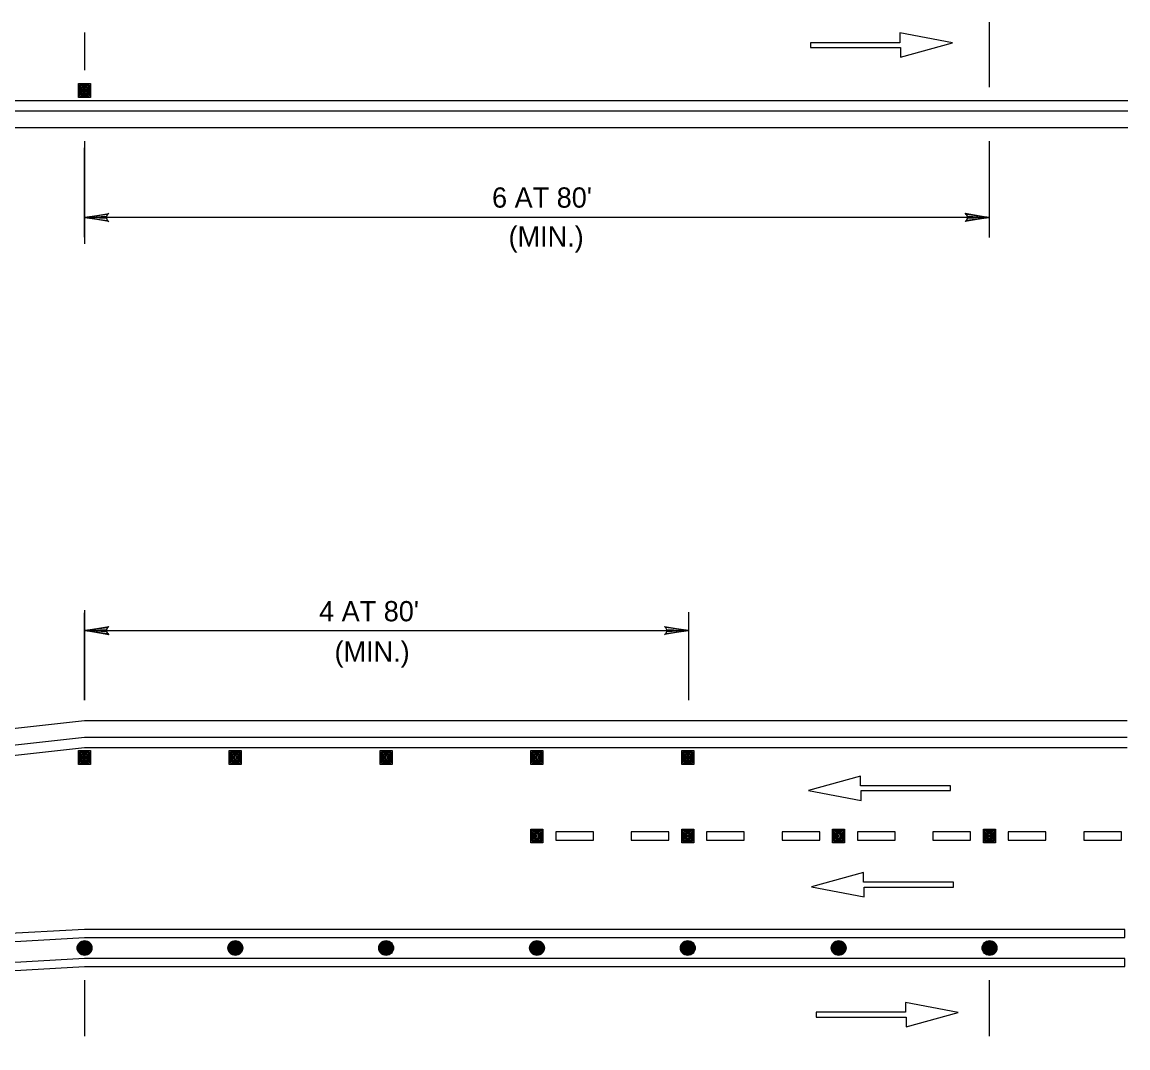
# Model space of a CAD drawing. Extents: x 639362 to 641108, y 298458 to 299646.
# Drawn here: x 639788.7 to 639952.7, y 298599.3 to 298751.3 of the extents above; entities that cross this region are included whole.
import ezdxf

# ---------------------------------------------------------------- set-up
doc = ezdxf.new("R2010")
doc.units = 0
doc.layers.add('2', color=7, linetype='Continuous')
doc.layers.add('3', color=7, linetype='Continuous')

# ---------------------------------------------------------------- blocks, each defined once
blk = doc.blocks.new('RARROW')
at = {"layer": '3'}
blk.add_lwpolyline([(-2.2695, 0.285), (-2.184875, 0.12075), (0, 0), (-2.2695, 0.285), (-2.38575, 0.384625), (0, 0), (-2.183125, -0.108), (-2.262875, -0.2705), (0, 0), (-2.38575, -0.379125), (-2.262875, -0.2705)], dxfattribs=at)

msp = doc.modelspace()

# ---------------------------------------------------------------- linework, layer by layer
at = {"layer": '2'}
for p, q in [((639932.2, 298741.66), (639932.2, 298751.3)), ((639798, 298749.76), (639798, 298744.18)), ((639926.74, 298748.22), (639918.93, 298749.7)), ((639918.93, 298749.7), (639918.93, 298748.25)), ((639918.93, 298748.25), (639905.69, 298748.25)), ((639905.69, 298748.25), (639905.69, 298747.55)), ((639905.69, 298747.55), (639919.02, 298747.55)), ((639919.02, 298746.1), (639926.74, 298748.22)), ((639919.02, 298747.55), (639919.02, 298746.1)), ((639797.11, 298740.14), (639797.11, 298742.18)), ((639797.11, 298742.18), (639798.88, 298742.18)), ((639797.28, 298740.32), (639797.28, 298742)), ((639797.28, 298742), (639798.7, 298742)), ((639797.46, 298740.5), (639797.46, 298741.83)), ((639797.46, 298741.83), (639798.53, 298741.83)), ((639797.64, 298740.67), (639797.64, 298741.65)), ((639797.64, 298741.65), (639798.35, 298741.65)), ((639797.82, 298740.85), (639797.82, 298741.47)), ((639797.82, 298741.47), (639798.17, 298741.47)), ((639798, 298741.03), (639798, 298741.29)), ((639798.17, 298741.47), (639798.17, 298740.85)), ((639798.35, 298741.65), (639798.35, 298740.67)), ((639798.53, 298741.83), (639798.53, 298740.5)), ((639798.7, 298742), (639798.7, 298740.32)), ((639798.88, 298742.18), (639798.88, 298740.14)), ((639431.35, 298739.66), (639952.74, 298739.66)), ((639798.88, 298740.14), (639797.11, 298740.14)), ((639798.7, 298740.32), (639797.28, 298740.32)), ((639798.53, 298740.5), (639797.46, 298740.5)), ((639798.35, 298740.67), (639797.64, 298740.67)), ((639798.17, 298740.85), (639797.82, 298740.85)), ((639431.35, 298738.16), (639952.74, 298738.16)), ((639431.35, 298735.66), (639952.74, 298735.66)), ((639798, 298733.66), (639798, 298718.46)), ((639932.2, 298719.36), (639932.2, 298733.66)), ((639798, 298719.43), (639798, 298732.66)), ((639932.2, 298722.36), (639798, 298722.36)), ((639797.99, 298664.16), (639797.99, 298650.81)), ((639798, 298650.81), (639798, 298663.74)), ((639887.61, 298650.81), (639887.61, 298663.83)), ((639798.01, 298661.11), (639887.61, 298661.11)), ((639585.9, 298624.2), (639797.99, 298647.81)), ((639797.99, 298647.81), (639951.12, 298647.81)), ((639797.99, 298647.81), (639952.64, 298647.81)), ((639585.9, 298621.7), (639797.99, 298645.31)), ((639797.99, 298645.31), (639951.12, 298645.31)), ((639797.99, 298645.31), (639952.64, 298645.31)), ((639585.9, 298620.2), (639797.99, 298643.81)), ((639797.11, 298641.29), (639797.11, 298643.33)), ((639797.11, 298643.33), (639798.88, 298643.33)), ((639797.28, 298641.47), (639797.28, 298643.16)), ((639797.28, 298643.16), (639798.7, 298643.16)), ((639797.46, 298641.65), (639797.46, 298642.98)), ((639797.46, 298642.98), (639798.53, 298642.98)), ((639797.64, 298641.83), (639797.64, 298642.8)), ((639797.64, 298642.8), (639798.35, 298642.8)), ((639797.82, 298642), (639797.82, 298642.62)), ((639797.82, 298642.62), (639798.17, 298642.62)), ((639797.99, 298643.81), (639951.12, 298643.81)), ((639797.99, 298643.81), (639952.64, 298643.81)), ((639798.17, 298642.62), (639798.17, 298642)), ((639798.35, 298642.8), (639798.35, 298641.83)), ((639798.53, 298642.98), (639798.53, 298641.65)), ((639798.7, 298643.16), (639798.7, 298641.47)), ((639798.88, 298643.33), (639798.88, 298641.29)), ((639819.47, 298641.29), (639819.47, 298643.33)), ((639819.47, 298643.33), (639821.25, 298643.33)), ((639819.65, 298641.47), (639819.65, 298643.16)), ((639819.65, 298643.16), (639821.07, 298643.16)), ((639819.83, 298641.65), (639819.83, 298642.98)), ((639819.83, 298642.98), (639820.89, 298642.98)), ((639820.01, 298641.83), (639820.01, 298642.8)), ((639820.01, 298642.8), (639820.72, 298642.8)), ((639820.18, 298642), (639820.18, 298642.62)), ((639820.18, 298642.62), (639820.54, 298642.62)), ((639820.54, 298642.62), (639820.54, 298642)), ((639820.72, 298642.8), (639820.72, 298641.83)), ((639820.89, 298642.98), (639820.89, 298641.65)), ((639821.07, 298643.16), (639821.07, 298641.47)), ((639821.25, 298643.33), (639821.25, 298641.29)), ((639841.84, 298641.29), (639841.84, 298643.33)), ((639841.84, 298643.33), (639843.62, 298643.33)), ((639842.02, 298641.47), (639842.02, 298643.16)), ((639842.02, 298643.16), (639843.44, 298643.16)), ((639842.2, 298641.65), (639842.2, 298642.98)), ((639842.2, 298642.98), (639843.26, 298642.98)), ((639842.37, 298641.83), (639842.37, 298642.8)), ((639842.37, 298642.8), (639843.08, 298642.8)), ((639842.55, 298642), (639842.55, 298642.62)), ((639842.55, 298642.62), (639842.91, 298642.62)), ((639842.91, 298642.62), (639842.91, 298642)), ((639843.08, 298642.8), (639843.08, 298641.83)), ((639843.26, 298642.98), (639843.26, 298641.65)), ((639843.44, 298643.16), (639843.44, 298641.47)), ((639843.62, 298643.33), (639843.62, 298641.29)), ((639864.21, 298641.29), (639864.21, 298643.33)), ((639864.21, 298643.33), (639865.98, 298643.33)), ((639864.39, 298641.47), (639864.39, 298643.16)), ((639864.39, 298643.16), (639865.81, 298643.16)), ((639864.56, 298641.65), (639864.56, 298642.98)), ((639864.56, 298642.98), (639865.63, 298642.98)), ((639864.74, 298641.83), (639864.74, 298642.8)), ((639864.74, 298642.8), (639865.45, 298642.8)), ((639864.92, 298642), (639864.92, 298642.62)), ((639864.92, 298642.62), (639865.27, 298642.62)), ((639865.27, 298642.62), (639865.27, 298642)), ((639865.45, 298642.8), (639865.45, 298641.83)), ((639865.63, 298642.98), (639865.63, 298641.65)), ((639865.81, 298643.16), (639865.81, 298641.47)), ((639865.98, 298643.33), (639865.98, 298641.29)), ((639886.58, 298641.29), (639886.58, 298643.33)), ((639886.58, 298643.33), (639888.35, 298643.33)), ((639886.75, 298641.47), (639886.75, 298643.16)), ((639886.75, 298643.16), (639888.17, 298643.16)), ((639886.93, 298641.65), (639886.93, 298642.98)), ((639886.93, 298642.98), (639888, 298642.98)), ((639887.11, 298641.83), (639887.11, 298642.8)), ((639887.11, 298642.8), (639887.82, 298642.8)), ((639887.29, 298642), (639887.29, 298642.62)), ((639887.29, 298642.62), (639887.64, 298642.62)), ((639887.64, 298642.62), (639887.64, 298642)), ((639887.82, 298642.8), (639887.82, 298641.83)), ((639888, 298642.98), (639888, 298641.65)), ((639888.17, 298643.16), (639888.17, 298641.47)), ((639888.35, 298643.33), (639888.35, 298641.29)), ((639798.88, 298641.29), (639797.11, 298641.29)), ((639798.7, 298641.47), (639797.28, 298641.47)), ((639798.53, 298641.65), (639797.46, 298641.65)), ((639798.35, 298641.83), (639797.64, 298641.83)), ((639798.17, 298642), (639797.82, 298642)), ((639798, 298642.18), (639798, 298642.45)), ((639821.25, 298641.29), (639819.47, 298641.29)), ((639821.07, 298641.47), (639819.65, 298641.47)), ((639820.89, 298641.65), (639819.83, 298641.65)), ((639820.72, 298641.83), (639820.01, 298641.83)), ((639820.54, 298642), (639820.18, 298642)), ((639820.36, 298642.18), (639820.36, 298642.45)), ((639843.62, 298641.29), (639841.84, 298641.29)), ((639843.44, 298641.47), (639842.02, 298641.47)), ((639843.26, 298641.65), (639842.2, 298641.65)), ((639843.08, 298641.83), (639842.37, 298641.83)), ((639842.91, 298642), (639842.55, 298642)), ((639842.73, 298642.18), (639842.73, 298642.45)), ((639865.98, 298641.29), (639864.21, 298641.29)), ((639865.81, 298641.47), (639864.39, 298641.47)), ((639865.63, 298641.65), (639864.56, 298641.65)), ((639865.45, 298641.83), (639864.74, 298641.83)), ((639865.27, 298642), (639864.92, 298642)), ((639865.1, 298642.18), (639865.1, 298642.45)), ((639888.35, 298641.29), (639886.58, 298641.29)), ((639888.17, 298641.47), (639886.75, 298641.47)), ((639888, 298641.65), (639886.93, 298641.65)), ((639887.82, 298641.83), (639887.11, 298641.83)), ((639887.64, 298642), (639887.29, 298642)), ((639887.47, 298642.18), (639887.47, 298642.45)), ((639913.08, 298639.53), (639905.36, 298637.42)), ((639913.08, 298638.09), (639913.08, 298639.53)), ((639926.41, 298638.09), (639913.08, 298638.09)), ((639926.41, 298637.39), (639926.41, 298638.09)), ((639905.36, 298637.42), (639913.16, 298635.94)), ((639913.16, 298635.94), (639913.16, 298637.39)), ((639913.16, 298637.39), (639926.41, 298637.39)), ((639864.21, 298629.65), (639864.21, 298631.69)), ((639864.21, 298631.69), (639865.98, 298631.69)), ((639864.39, 298629.83), (639864.39, 298631.51)), ((639864.39, 298631.51), (639865.81, 298631.51)), ((639864.56, 298630), (639864.56, 298631.33)), ((639864.56, 298631.33), (639865.63, 298631.33)), ((639864.74, 298630.18), (639864.74, 298631.15)), ((639864.74, 298631.15), (639865.45, 298631.15)), ((639865.45, 298631.15), (639865.45, 298630.18)), ((639865.63, 298631.33), (639865.63, 298630)), ((639865.81, 298631.51), (639865.81, 298629.83)), ((639865.98, 298631.69), (639865.98, 298629.65)), ((639873.49, 298631.27), (639867.89, 298631.27)), ((639867.89, 298631.27), (639867.89, 298630.07)), ((639873.49, 298630.07), (639873.49, 298631.27)), ((639884.67, 298631.27), (639879.08, 298631.27)), ((639879.08, 298631.27), (639879.08, 298630.07)), ((639884.67, 298630.07), (639884.67, 298631.27)), ((639886.58, 298629.65), (639886.58, 298631.69)), ((639886.58, 298631.69), (639888.35, 298631.69)), ((639886.75, 298629.83), (639886.75, 298631.51)), ((639886.75, 298631.51), (639888.17, 298631.51)), ((639886.93, 298630), (639886.93, 298631.33)), ((639886.93, 298631.33), (639888, 298631.33)), ((639887.11, 298630.18), (639887.11, 298631.15)), ((639887.11, 298631.15), (639887.82, 298631.15)), ((639887.82, 298631.15), (639887.82, 298630.18)), ((639888, 298631.33), (639888, 298630)), ((639888.17, 298631.51), (639888.17, 298629.83)), ((639888.35, 298631.69), (639888.35, 298629.65)), ((639895.85, 298631.27), (639890.26, 298631.27)), ((639890.26, 298631.27), (639890.26, 298630.07)), ((639895.85, 298630.07), (639895.85, 298631.27)), ((639907.04, 298631.27), (639901.45, 298631.27)), ((639901.45, 298631.27), (639901.45, 298630.07)), ((639907.04, 298630.07), (639907.04, 298631.27)), ((639908.94, 298629.65), (639908.94, 298631.69)), ((639908.94, 298631.69), (639910.72, 298631.69)), ((639909.12, 298629.83), (639909.12, 298631.51)), ((639909.12, 298631.51), (639910.54, 298631.51)), ((639909.3, 298630), (639909.3, 298631.33)), ((639909.3, 298631.33), (639910.36, 298631.33)), ((639909.48, 298630.18), (639909.48, 298631.15)), ((639909.48, 298631.15), (639910.19, 298631.15)), ((639910.19, 298631.15), (639910.19, 298630.18)), ((639910.36, 298631.33), (639910.36, 298630)), ((639910.54, 298631.51), (639910.54, 298629.83)), ((639910.72, 298631.69), (639910.72, 298629.65)), ((639918.22, 298631.27), (639912.63, 298631.27)), ((639912.63, 298631.27), (639912.63, 298630.07)), ((639918.22, 298630.07), (639918.22, 298631.27)), ((639929.41, 298631.27), (639923.81, 298631.27)), ((639923.81, 298631.27), (639923.81, 298630.07)), ((639929.41, 298630.07), (639929.41, 298631.27)), ((639931.31, 298629.65), (639931.31, 298631.69)), ((639931.31, 298631.69), (639933.09, 298631.69)), ((639931.49, 298629.83), (639931.49, 298631.51)), ((639931.49, 298631.51), (639932.91, 298631.51)), ((639931.67, 298630), (639931.67, 298631.33)), ((639931.67, 298631.33), (639932.73, 298631.33)), ((639931.84, 298630.18), (639931.84, 298631.15)), ((639931.84, 298631.15), (639932.55, 298631.15)), ((639932.55, 298631.15), (639932.55, 298630.18)), ((639932.73, 298631.33), (639932.73, 298630)), ((639932.91, 298631.51), (639932.91, 298629.83)), ((639933.09, 298631.69), (639933.09, 298629.65)), ((639940.59, 298631.27), (639935, 298631.27)), ((639935, 298631.27), (639935, 298630.07)), ((639940.59, 298630.07), (639940.59, 298631.27)), ((639951.77, 298631.27), (639946.18, 298631.27)), ((639946.18, 298631.27), (639946.18, 298630.07)), ((639951.77, 298630.07), (639951.77, 298631.27)), ((639865.98, 298629.65), (639864.21, 298629.65)), ((639865.81, 298629.83), (639864.39, 298629.83)), ((639865.63, 298630), (639864.56, 298630)), ((639865.45, 298630.18), (639864.74, 298630.18)), ((639864.92, 298630.35), (639864.92, 298630.98)), ((639864.92, 298630.98), (639865.27, 298630.98)), ((639865.27, 298630.35), (639864.92, 298630.35)), ((639865.1, 298630.53), (639865.1, 298630.8)), ((639865.27, 298630.98), (639865.27, 298630.35)), ((639867.89, 298630.07), (639873.49, 298630.07)), ((639879.08, 298630.07), (639884.67, 298630.07)), ((639888.35, 298629.65), (639886.58, 298629.65)), ((639888.17, 298629.83), (639886.75, 298629.83)), ((639888, 298630), (639886.93, 298630)), ((639887.82, 298630.18), (639887.11, 298630.18)), ((639887.29, 298630.35), (639887.29, 298630.98)), ((639887.29, 298630.98), (639887.64, 298630.98)), ((639887.64, 298630.35), (639887.29, 298630.35)), ((639887.47, 298630.53), (639887.47, 298630.8)), ((639887.64, 298630.98), (639887.64, 298630.35)), ((639890.26, 298630.07), (639895.85, 298630.07)), ((639901.45, 298630.07), (639907.04, 298630.07)), ((639910.72, 298629.65), (639908.94, 298629.65)), ((639910.54, 298629.83), (639909.12, 298629.83)), ((639910.36, 298630), (639909.3, 298630)), ((639910.19, 298630.18), (639909.48, 298630.18)), ((639909.65, 298630.35), (639909.65, 298630.98)), ((639909.65, 298630.98), (639910.01, 298630.98)), ((639910.01, 298630.35), (639909.65, 298630.35)), ((639909.83, 298630.53), (639909.83, 298630.8)), ((639910.01, 298630.98), (639910.01, 298630.35)), ((639912.63, 298630.07), (639918.22, 298630.07)), ((639923.81, 298630.07), (639929.41, 298630.07)), ((639933.09, 298629.65), (639931.31, 298629.65)), ((639932.91, 298629.83), (639931.49, 298629.83)), ((639932.73, 298630), (639931.67, 298630)), ((639932.55, 298630.18), (639931.84, 298630.18)), ((639932.02, 298630.35), (639932.02, 298630.98)), ((639932.02, 298630.98), (639932.38, 298630.98)), ((639932.38, 298630.35), (639932.02, 298630.35)), ((639932.2, 298630.53), (639932.2, 298630.8)), ((639932.38, 298630.98), (639932.38, 298630.35)), ((639935, 298630.07), (639940.59, 298630.07)), ((639946.18, 298630.07), (639951.77, 298630.07)), ((639913.53, 298625.26), (639905.81, 298623.15)), ((639913.53, 298623.82), (639913.53, 298625.26)), ((639905.81, 298623.15), (639913.61, 298621.67)), ((639926.86, 298623.82), (639913.53, 298623.82)), ((639913.61, 298621.67), (639913.61, 298623.11)), ((639913.61, 298623.11), (639926.86, 298623.11)), ((639926.86, 298623.11), (639926.86, 298623.82)), ((639797.98, 298616.83), (639585.9, 298604.78)), ((639952.26, 298616.83), (639797.98, 298616.83)), ((639798, 298616.83), (639797.99, 298616.83)), ((639952.26, 298615.63), (639952.26, 298616.83)), ((639585.93, 298603.58), (639798.02, 298615.63)), ((639798.02, 298615.63), (639952.26, 298615.63)), ((639797.98, 298612.52), (639585.9, 298600.47)), ((639952.26, 298612.52), (639797.98, 298612.52)), ((639952.26, 298611.32), (639952.26, 298612.52)), ((639585.93, 298599.27), (639798.02, 298611.32)), ((639798.02, 298611.32), (639952.26, 298611.32)), ((639798, 298609.32), (639798, 298601)), ((639932.2, 298601), (639932.2, 298609.32)), ((639927.57, 298604.51), (639919.76, 298605.99)), ((639919.76, 298605.99), (639919.76, 298604.55)), ((639919.76, 298604.55), (639906.52, 298604.55)), ((639906.52, 298604.55), (639906.52, 298603.84)), ((639906.52, 298603.84), (639919.84, 298603.84)), ((639919.84, 298602.4), (639927.57, 298604.51)), ((639919.84, 298603.84), (639919.84, 298602.4))]:
    msp.add_line(p, q, dxfattribs=at)
for centre, radius in [((639798.01, 298614.07), 1.1), ((639798.01, 298614.07), 1.02), ((639798.01, 298614.07), 0.946), ((639798.01, 298614.07), 0.868), ((639798.01, 298614.07), 0.789), ((639798.01, 298614.07), 0.711), ((639820.36, 298614.07), 1.1), ((639820.36, 298614.07), 1.02), ((639820.36, 298614.07), 0.946), ((639820.36, 298614.07), 0.868), ((639820.36, 298614.07), 0.789), ((639820.36, 298614.07), 0.711), ((639842.73, 298614.07), 1.1), ((639842.73, 298614.07), 1.02), ((639842.73, 298614.07), 0.946), ((639842.73, 298614.07), 0.868), ((639842.73, 298614.07), 0.789), ((639842.73, 298614.07), 0.711), ((639865.1, 298614.07), 1.1), ((639865.1, 298614.07), 1.02), ((639865.1, 298614.07), 0.946), ((639865.1, 298614.07), 0.868), ((639865.1, 298614.07), 0.789), ((639865.1, 298614.07), 0.711), ((639887.47, 298614.07), 1.1), ((639887.47, 298614.07), 1.02), ((639887.47, 298614.07), 0.946), ((639887.47, 298614.07), 0.868), ((639887.47, 298614.07), 0.789), ((639887.47, 298614.07), 0.711), ((639909.85, 298614.07), 1.1), ((639909.85, 298614.07), 1.02), ((639909.85, 298614.07), 0.946), ((639909.85, 298614.07), 0.868), ((639909.85, 298614.07), 0.789), ((639909.85, 298614.07), 0.711), ((639932.22, 298614.07), 1.1), ((639932.22, 298614.07), 1.02), ((639932.22, 298614.07), 0.946), ((639932.22, 298614.07), 0.868), ((639932.22, 298614.07), 0.789), ((639932.22, 298614.07), 0.711), ((639798.01, 298614.07), 0.633), ((639798.01, 298614.07), 0.554), ((639798.01, 298614.07), 0.476), ((639798.01, 298614.07), 0.398), ((639798.01, 298614.07), 0.32), ((639798.01, 298614.07), 0.241), ((639798.01, 298614.07), 0.163), ((639798.01, 298614.07), 0.0846), ((639820.36, 298614.07), 0.633), ((639820.36, 298614.07), 0.554), ((639820.36, 298614.07), 0.476), ((639820.36, 298614.07), 0.398), ((639820.36, 298614.07), 0.32), ((639820.36, 298614.07), 0.241), ((639820.36, 298614.07), 0.163), ((639820.36, 298614.07), 0.0846), ((639842.73, 298614.07), 0.633), ((639842.73, 298614.07), 0.554), ((639842.73, 298614.07), 0.476), ((639842.73, 298614.07), 0.398), ((639842.73, 298614.07), 0.32), ((639842.73, 298614.07), 0.241), ((639842.73, 298614.07), 0.163), ((639842.73, 298614.07), 0.0846), ((639865.1, 298614.07), 0.633), ((639865.1, 298614.07), 0.554), ((639865.1, 298614.07), 0.476), ((639865.1, 298614.07), 0.398), ((639865.1, 298614.07), 0.32), ((639865.1, 298614.07), 0.241), ((639865.1, 298614.07), 0.163), ((639865.1, 298614.07), 0.0846), ((639887.47, 298614.07), 0.633), ((639887.47, 298614.07), 0.554), ((639887.47, 298614.07), 0.476), ((639887.47, 298614.07), 0.398), ((639887.47, 298614.07), 0.32), ((639887.47, 298614.07), 0.241), ((639887.47, 298614.07), 0.163), ((639887.47, 298614.07), 0.0846), ((639909.85, 298614.07), 0.633), ((639909.85, 298614.07), 0.554), ((639909.85, 298614.07), 0.476), ((639909.85, 298614.07), 0.398), ((639909.85, 298614.07), 0.32), ((639909.85, 298614.07), 0.241), ((639909.85, 298614.07), 0.163), ((639909.85, 298614.07), 0.0846), ((639932.22, 298614.07), 0.633), ((639932.22, 298614.07), 0.554), ((639932.22, 298614.07), 0.476), ((639932.22, 298614.07), 0.398), ((639932.22, 298614.07), 0.32), ((639932.22, 298614.07), 0.241), ((639932.22, 298614.07), 0.163), ((639932.22, 298614.07), 0.0846)]:
    msp.add_circle(centre, radius, dxfattribs=at)

# ---------------------------------------------------------------- block references
at = {"layer": '2', "xscale": 1.5089217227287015, "yscale": 1.5711553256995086, "rotation": 180}
for p in [(639798, 298722.36), (639798.01, 298661.11)]:
    msp.add_blockref('RARROW', p, dxfattribs=at)
at = {"layer": '2', "xscale": 1.5089217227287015, "yscale": 1.5711553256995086}
for p in [(639932.2, 298722.36), (639887.61, 298661.11)]:
    msp.add_blockref('RARROW', p, dxfattribs=at)

# ---------------------------------------------------------------- texts
at = {"layer": '2'}
for s, p in [("6 AT 80'", (639858.44, 298723.8)), ('(MIN.)', (639860.89, 298718.03)), ("4 AT 80'", (639832.79, 298662.49)), ('(MIN.)', (639835.08, 298656.51))]:
    msp.add_text(s, height=3, dxfattribs=at).set_placement(p)

doc.saveas('drawing.dxf')
